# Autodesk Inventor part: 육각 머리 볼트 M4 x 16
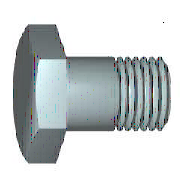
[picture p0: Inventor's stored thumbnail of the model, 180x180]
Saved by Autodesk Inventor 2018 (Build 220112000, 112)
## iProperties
IsCustomPart: 0
Created: 2012-02
Part Number: 육각 머리 볼트 M4 x 16
Material: 강철, 연강
Description: 6각 머리 볼트 및 6각 머리 나사
Document SubType Name: Modeling
Standard: KS B 1002
Designer: mduedu
Standards Organization: KS
Language: ko-KR
Size Designation: A + B M4 x 16
Categories: <MemberInstance><Categories><Category DisplayName="조임쇠" InternalName="e4da775c-781d-43d5-af7c-5136215cf5a6" Mnemonic="FSTN"><Category DisplayName="볼트" InternalN
Density: 7.85 g/cm^3
Appearance: 강철
Mass: 2.45173 g
Surface Area: 3.4613 cm^2
Volume: 0.312323 cm^3
Author: mduedu
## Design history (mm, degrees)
sketch "스케치1"
  geometry: L1 (0, 2.94)-(0, 2); L2 (2.1, 2)-(16, 2); L3 (16, 2)-(16, 0); L4 (16, 0)-(-0.4, 0); L5 (-3.68, 0)-(19.28, 0) reference; L6 (-0.4, 0)-(-0.4, 2.94); L7 (-0.4, 2.94)-(0, 2.94); L8 (2.1, 2)-(1.67, 2); L9 (1.67, 2)-(0, 2); L10 (0, -0.588)-(0, 3.528) reference
  constraints: 16 end point, 2 collinear, 2 perpendicular, 1 parallel
  dimensions: "d0" = 16 distance between parallel lines of L3 L1 (= NLG); "d1" = 13.9 distance from line of L2.start L3 (= GEL); "d2" = 4 diameter of L2 L4 (= GD); "d9" = 0.4001 distance between parallel lines of L6 L1 (computed from SD); "d10" = 5.88 diameter of L7 L4 (= SD2); "d13" = 0.42952 distance of L2.start L8.end (computed from GAL); "d14" = 4 diameter of L9 L4 (= BDM)
revolve "본체" sketch "스케치1" stored, may be unused: angle "d12" = 90 deg
sketch "스케치2"
  geometry: L1 (0, 4.041)-(3.5, 2.021); L2 (3.5, 2.021)-(3.5, -2.021); L3 (3.5, -2.021)-(0, -4.041); L4 (0, -4.041)-(-3.5, -2.021); L5 (-3.5, -2.021)-(-3.5, 2.021); L6 (-3.5, 2.021)-(0, 4.041); 2 further points
  constraints: 12 end point, 1 coincident, 1 vertical, 11 other
  dimensions: "d11" = 7 distance between parallel lines of L5 L2 (= SW)
extrude "머리" join sketch "스케치2" distance "d3" = 2.4 (= KOH - SD); taper "d4" = 0 deg
sketch "스케치4"
  geometry: L1 (-2.8, 3.5)-(-2.8, 4.041); L2 (-2.8, 4.041)-(-2.487, 4.041); L3 (-2.487, 4.041)-(-2.8, 3.5); L4 (-3.28, 0)-(0.08, 0) reference; L5 (-0.4, 4.041)-(-2.8, 4.041) reference; L6 (-2.8, 2.021)-(-2.8, 4.041) reference
  constraints: 6 end point, 2 collinear, 1 perpendicular, 1 vertical
  dimensions: "d5" = 30 deg angle of L3 L1 (= ANG1); "d19" = 7 diameter of L1.start L4 (= SW0)
revolve "모따기1" sketch "스케치4" stored, may be unused: angle "d21" = 90 deg
workplane "Work Plane1"
body "Solid1"
feature "스레드" dims "d15" = 13.9 (= GEL), "d16" = 0
chamfer "모따기2" distance "d6" = 0.42941 (= -0.5 x SPD + 0.5 x GD); stored, may be unused: second distance "d7" = 0.42952 (computed from GUL), angle "d55" = 45 deg
other parameters: "NLG" = 16 [user parameter; used in 1 equation term], "GD" = 4 (= NND) [user parameter; used in 2 equation terms], "BDM" = 4 (= NND) [user parameter; used in 1 equation term], "KOH" = 2.8 [user parameter; used in 1 equation term], "GEL" = 13.9 [user parameter; used in 2 equation terms], "SW" = 7 [user parameter; used in 3 equation terms], "SW0" = 7 (= SW) [user parameter; used in 1 equation term], "SPD" = 3.14117 (= NND - 1.2269 x PTC) [user parameter; used in 1 equation term], "SD2" = 5.88 (= SDH) [user parameter; used in 1 equation term], "SD" = 0.4 [user parameter; used in 2 equation terms], "ANG1" = 30 deg [user parameter; used in 1 equation term], "GAL" = 0.42941 (= 0.61345 x PTC) [user parameter; used in 1 equation term], "GUL" = 0.42941 (= 0.61345 x PTC) [user parameter; used in 1 equation term], "d8" = 0, "RR" = 0.2 [user parameter], "d57" = 0, "d58" = 0, "TPU" = 14.28571 (computed from PTC) [user parameter], "GD1" = 3.14117 (= THREADDIA - 1.2269 x PTC) [user parameter], "THREADDIA" = 4 [user parameter; used in 1 equation term], "SDH" = 5.88 [user parameter; used in 1 equation term], "SDHG" = 2.1 [user parameter], "TOA" = 30 deg [user parameter], "PTC" = 0.7 [user parameter; used in 5 equation terms], "NND" = 4 [user parameter; used in 3 equation terms], "E0" = 8.085 (= 1.155 x SW) [user parameter]
